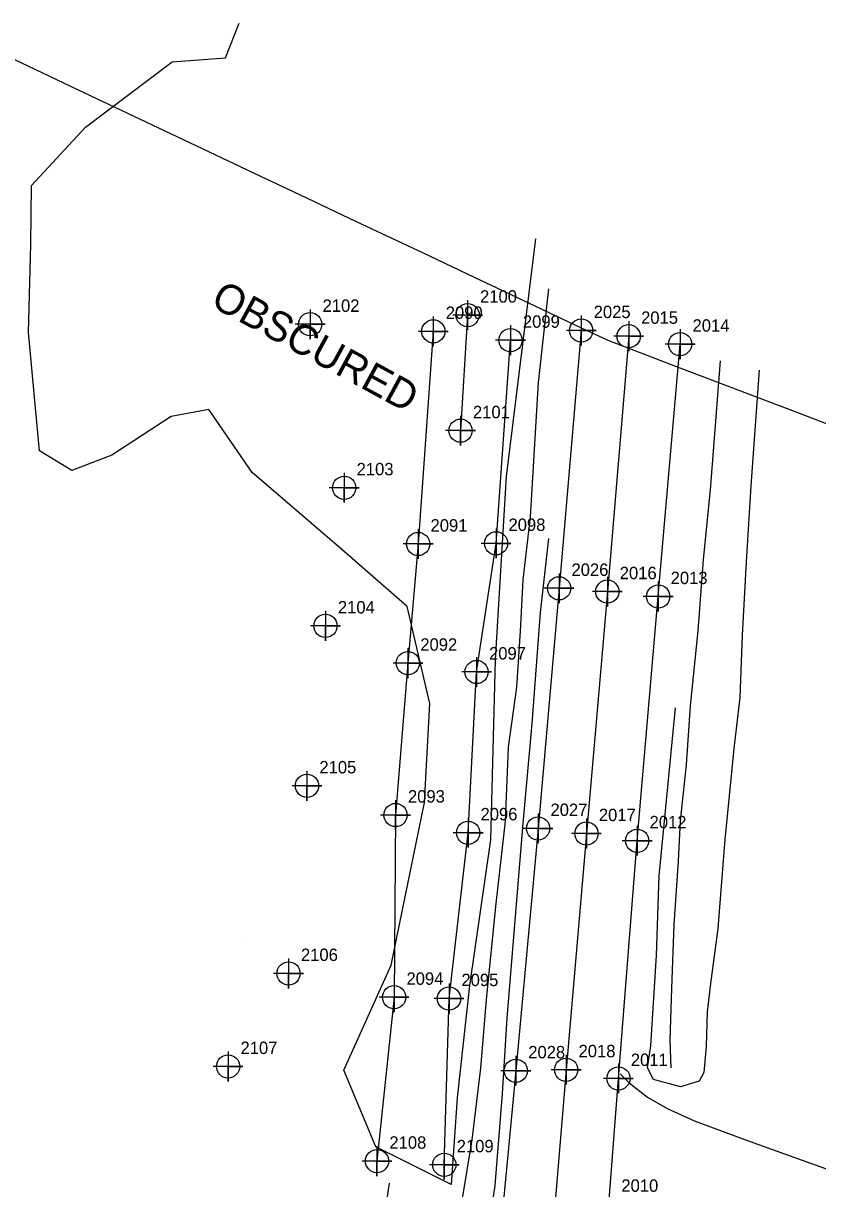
# Model space of a CAD drawing. Extents: x 1497074 to 1501343, y 481943 to 486114.
# Drawn here: x 1499836.8 to 1499996.8, y 482891.4 to 483126.1 of the extents above; entities that cross this region are included whole.
import ezdxf

# ---------------------------------------------------------------- set-up
doc = ezdxf.new("R2010")
doc.units = 0
for name, color, linetype in [('Exist DTM Breakline', 7, 'Continuous'), ('Exist DTM Breakline Cogo Number', 7, 'Continuous'), ('Exist DTM Breakline Cogo Point CELL', 7, 'Continuous'), ('Exist DTM Crownline', 7, 'Continuous'), ('Exist DTM Crownline Cogo Number', 7, 'Continuous'), ('Exist DTM Crownline Cogo Point CELL', 7, 'Continuous'), ('Exist DTM Regular Point CELL', 7, 'Continuous'), ('Exist DTM Regular Point Cogo Number', 7, 'Continuous'), ('Exist Roads EOP', 7, 'Continuous'), ('Exist Roads EOP Cogo Number', 7, 'Continuous'), ('Exist Roads EOP Cogo Point CELL', 7, 'Continuous'), ('PH Exist DTM Boundary', 7, 'Continuous'), ('PH Exist DTM Breakline', 7, 'Continuous'), ('PH Exist DTM Obscure Area', 7, 'Continuous'), ('PH Exist DTM Obscure Area Text', 7, 'Continuous'), ('PH Exist DTM Point', 7, 'Continuous')]:
    doc.layers.add(name, color=color, linetype=linetype)

msp = doc.modelspace()

# ---------------------------------------------------------------- linework, layer by layer
at = {"layer": 'Exist DTM Breakline'}
msp.add_line((1499926.3, 483067.35), (1499924.87, 483044.07), dxfattribs=at)
for points in [[(1499919.39, 483064.07), (1499916.33, 483021.24), (1499914.27, 482997.24), (1499911.78, 482966.64), (1499911.48, 482929.95), (1499908.04, 482896.93)], [(1499921.6, 482896.2), (1499922.55, 482929.68), (1499926.4, 482963.07), (1499928.11, 482995.46), (1499932.03, 483021.37), (1499934.93, 483062.29)]]:
    msp.add_lwpolyline(points, dxfattribs=at)
at = {"layer": 'Exist DTM Breakline Cogo Point CELL'}
for points in [[(1499926.3, 483070.35), (1499926.3, 483064.35), (1499926.3, 483067.35), (1499929.3, 483067.35), (1499923.3, 483067.35)], [(1499919.39, 483067.07), (1499919.39, 483061.07), (1499919.39, 483064.07), (1499922.39, 483064.07), (1499916.39, 483064.07)], [(1499934.93, 483065.29), (1499934.93, 483059.29), (1499934.93, 483062.29), (1499937.93, 483062.29), (1499931.93, 483062.29)], [(1499924.87, 483047.07), (1499924.87, 483041.07), (1499924.87, 483044.07), (1499927.87, 483044.07), (1499921.87, 483044.07)], [(1499916.33, 483024.24), (1499916.33, 483018.24), (1499916.33, 483021.24), (1499919.33, 483021.24), (1499913.33, 483021.24)], [(1499932.03, 483024.37), (1499932.03, 483018.37), (1499932.03, 483021.37), (1499935.03, 483021.37), (1499929.03, 483021.37)], [(1499914.27, 483000.24), (1499914.27, 482994.24), (1499914.27, 482997.24), (1499917.27, 482997.24), (1499911.27, 482997.24)], [(1499928.11, 482998.46), (1499928.11, 482992.46), (1499928.11, 482995.46), (1499931.11, 482995.46), (1499925.11, 482995.46)], [(1499911.78, 482969.64), (1499911.78, 482963.64), (1499911.78, 482966.64), (1499914.78, 482966.64), (1499908.78, 482966.64)], [(1499926.4, 482966.07), (1499926.4, 482960.07), (1499926.4, 482963.07), (1499929.4, 482963.07), (1499923.4, 482963.07)], [(1499911.48, 482932.95), (1499911.48, 482926.95), (1499911.48, 482929.95), (1499914.48, 482929.95), (1499908.48, 482929.95)], [(1499922.55, 482932.68), (1499922.55, 482926.68), (1499922.55, 482929.68), (1499925.55, 482929.68), (1499919.55, 482929.68)], [(1499908.04, 482899.93), (1499908.04, 482893.93), (1499908.04, 482896.93), (1499911.04, 482896.93), (1499905.04, 482896.93)], [(1499921.6, 482899.2), (1499921.6, 482893.2), (1499921.6, 482896.2), (1499924.6, 482896.2), (1499918.6, 482896.2)]]:
    msp.add_lwpolyline(points, dxfattribs=at)
for centre in [(1499926.3, 483067.35), (1499919.39, 483064.07), (1499934.93, 483062.29), (1499924.87, 483044.07), (1499916.33, 483021.24), (1499932.03, 483021.37), (1499914.27, 482997.24), (1499928.11, 482995.46), (1499911.78, 482966.64), (1499926.4, 482963.07), (1499911.48, 482929.95), (1499922.55, 482929.68), (1499908.04, 482896.93), (1499921.6, 482896.2)]:
    msp.add_circle(centre, 2.34, dxfattribs=at)
at = {"layer": 'Exist DTM Crownline'}
msp.add_lwpolyline([(1499958.74, 483063.09), (1499954.44, 483011.65), (1499950.23, 482962.92), (1499946.14, 482915.34), (1499941.96, 482865.48), (1499937.54, 482815.31), (1499932.53, 482760.35), (1499932.32, 482757.09)], dxfattribs=at)
at = {"layer": 'Exist DTM Crownline Cogo Point CELL'}
for points in [[(1499958.74, 483066.09), (1499958.74, 483060.09), (1499958.74, 483063.09), (1499961.74, 483063.09), (1499955.74, 483063.09)], [(1499954.44, 483014.65), (1499954.44, 483008.65), (1499954.44, 483011.65), (1499957.44, 483011.65), (1499951.44, 483011.65)], [(1499950.23, 482965.92), (1499950.23, 482959.92), (1499950.23, 482962.92), (1499953.23, 482962.92), (1499947.23, 482962.92)], [(1499946.14, 482918.34), (1499946.14, 482912.34), (1499946.14, 482915.34), (1499949.14, 482915.34), (1499943.14, 482915.34)]]:
    msp.add_lwpolyline(points, dxfattribs=at)
for centre in [(1499958.74, 483063.09), (1499954.44, 483011.65), (1499950.23, 482962.92), (1499946.14, 482915.34)]:
    msp.add_circle(centre, 2.34, dxfattribs=at)
at = {"layer": 'Exist DTM Regular Point CELL'}
for points in [[(1499894.58, 483068.5), (1499894.58, 483062.5), (1499894.58, 483065.5), (1499897.58, 483065.5), (1499891.58, 483065.5)], [(1499901.44, 483035.57), (1499901.44, 483029.57), (1499901.44, 483032.57), (1499904.44, 483032.57), (1499898.44, 483032.57)], [(1499897.67, 483007.75), (1499897.67, 483001.75), (1499897.67, 483004.75), (1499900.67, 483004.75), (1499894.67, 483004.75)], [(1499893.94, 482975.53), (1499893.94, 482969.53), (1499893.94, 482972.53), (1499896.94, 482972.53), (1499890.94, 482972.53)], [(1499890.23, 482937.73), (1499890.23, 482931.73), (1499890.23, 482934.73), (1499893.23, 482934.73), (1499887.23, 482934.73)], [(1499878.05, 482919), (1499878.05, 482913), (1499878.05, 482916), (1499881.05, 482916), (1499875.05, 482916)]]:
    msp.add_lwpolyline(points, dxfattribs=at)
for centre in [(1499894.58, 483065.5), (1499901.44, 483032.57), (1499897.67, 483004.75), (1499893.94, 482972.53), (1499890.23, 482934.73), (1499878.05, 482916)]:
    msp.add_circle(centre, 2.34, dxfattribs=at)
at = {"layer": 'Exist Roads EOP'}
for points in [[(1499949.19, 483064.24), (1499944.72, 483012.31), (1499940.49, 482963.95), (1499936.01, 482915.13), (1499931.45, 482867.17), (1499924.58, 482816.71), (1499922.02, 482806.45), (1499917.89, 482798.05), (1499910.37, 482788.35), (1499905.04, 482784.05), (1499895.66, 482779.46), (1499886.2, 482778), (1499874.11, 482778.69), (1499823.96, 482797.88), (1499778.75, 482816.38), (1499731.6, 482836.87), (1499686.89, 482857.05)], [(1500333.95, 482612.22), (1500284.36, 482629.66), (1500236.85, 482646.79), (1500185.72, 482665.19), (1500183.6, 482666.66), (1500153.81, 482677.07), (1500131.68, 482684.8), (1500082.43, 482702.46), (1500031.71, 482720.79), (1499985.76, 482737.42), (1499982.67, 482738.92), (1499980.46, 482741.68), (1499966.94, 482755.42), (1499959.88, 482766), (1499955.46, 482776.15), (1499952.81, 482784.59), (1499951.94, 482792.64), (1499951.08, 482814.55), (1499953.05, 482864.42), (1499954.76, 482888.25), (1499956.67, 482913.59), (1499960.45, 482961.46), (1499964.69, 483010.66), (1499969.1, 483061.5)]]:
    msp.add_lwpolyline(points, dxfattribs=at)
at = {"layer": 'Exist Roads EOP Cogo Point CELL'}
for points in [[(1499949.19, 483067.24), (1499949.19, 483061.24), (1499949.19, 483064.24), (1499952.19, 483064.24), (1499946.19, 483064.24)], [(1499969.1, 483064.5), (1499969.1, 483058.5), (1499969.1, 483061.5), (1499972.1, 483061.5), (1499966.1, 483061.5)], [(1499944.72, 483015.31), (1499944.72, 483009.31), (1499944.72, 483012.31), (1499947.72, 483012.31), (1499941.72, 483012.31)], [(1499964.69, 483013.66), (1499964.69, 483007.66), (1499964.69, 483010.66), (1499967.69, 483010.66), (1499961.69, 483010.66)], [(1499940.49, 482966.95), (1499940.49, 482960.95), (1499940.49, 482963.95), (1499943.49, 482963.95), (1499937.49, 482963.95)], [(1499960.45, 482964.46), (1499960.45, 482958.46), (1499960.45, 482961.46), (1499963.45, 482961.46), (1499957.45, 482961.46)], [(1499936.01, 482918.13), (1499936.01, 482912.13), (1499936.01, 482915.13), (1499939.01, 482915.13), (1499933.01, 482915.13)], [(1499956.67, 482916.59), (1499956.67, 482910.59), (1499956.67, 482913.59), (1499959.67, 482913.59), (1499953.67, 482913.59)]]:
    msp.add_lwpolyline(points, dxfattribs=at)
for centre in [(1499949.19, 483064.24), (1499969.1, 483061.5), (1499944.72, 483012.31), (1499964.69, 483010.66), (1499940.49, 482963.95), (1499960.45, 482961.46), (1499936.01, 482915.13), (1499956.67, 482913.59)]:
    msp.add_circle(centre, 2.34, dxfattribs=at)
at = {"layer": 'PH Exist DTM Boundary'}
msp.add_lwpolyline([(1500009.09, 483041.44), (1499993.01, 483047.57), (1499989.09, 483049.06), (1499982.72, 483051.49), (1499969.09, 483056.68), (1499960.7, 483059.88), (1499954.58, 483062.21), (1499954.58, 483062.21), (1499949.09, 483064.81), (1499934.96, 483071.49), (1499930.97, 483073.37), (1499929.09, 483074.27), (1499917.39, 483079.8), (1499909.09, 483083.72), (1499903.81, 483086.22), (1499892.66, 483091.49), (1499889.09, 483093.18), (1499885.89, 483094.69), (1499869.09, 483102.63), (1499850.36, 483111.49), (1499849.09, 483112.09), (1499847.95, 483112.63), (1499829.09, 483121.55)], dxfattribs=at)
at = {"layer": 'PH Exist DTM Breakline'}
for points in [[(1499942.62, 483072.62), (1499940.52, 483053.77), (1499938.93, 483026.68), (1499937.41, 483014.04), (1499936.89, 483003.67), (1499936.16, 482992.43), (1499934.46, 482980.32), (1499933.85, 482965.43), (1499931.98, 482948.82), (1499930.01, 482929.49), (1499928.87, 482915.66), (1499927.12, 482901.19), (1499925.17, 482889.42)], [(1499984.99, 483056.22), (1499983.34, 483032.93), (1499982.39, 483017.66), (1499981.57, 483002.88), (1499981.1, 482990.35), (1499979.94, 482980.07), (1499979, 482970.51), (1499978.11, 482961.71), (1499977.49, 482954.07), (1499976.72, 482943.79), (1499975.22, 482932.69), (1499974.53, 482927.02), (1499974.33, 482920.01), (1499973.86, 482914.75), (1499972.94, 482913.06), (1499969.19, 482911.91), (1499963.77, 482913.35), (1499962.55, 482915.74), (1499963.2, 482920.19)], [(1499977.14, 483058.13), (1499975.18, 483032.14), (1499973.75, 483018.11), (1499972.64, 483003.76), (1499971.14, 482988.67), (1499970.31, 482976.78), (1499969.08, 482965.49), (1499968.72, 482957.36), (1499967.83, 482944.57), (1499967.34, 482931.7), (1499967.05, 482921.32), (1499967.22, 482915.69)], [(1499881.57, 482782.86), (1499889.62, 482782.75), (1499896.56, 482784.64), (1499903.43, 482787.74), (1499909.34, 482792.34), (1499913.56, 482798.2), (1499917.47, 482803.77), (1499919.36, 482810.89), (1499921.77, 482822.35), (1499923.8, 482835.12), (1499925.62, 482847.36), (1499928.12, 482864.6), (1499929.76, 482877.93), (1499931.83, 482891.99), (1499933.34, 482910.51), (1499934.27, 482925.74), (1499937.4, 482964.22), (1499939.33, 482985.05), (1499941.01, 483007.43), (1499942.66, 483022.35)], [(1499963.2, 482920.19), (1499964.31, 482938.35), (1499964.9, 482954.39), (1499966.62, 482972.3), (1499968.19, 482988.25)], [(1499957.02, 482914.54), (1499958.81, 482912.69), (1499962.54, 482909.78), (1499966.51, 482907.56), (1499972.1, 482905.01), (1499983.23, 482900.88), (1499997.95, 482895.57), (1500012.89, 482890.28), (1500036.47, 482882.13), (1500053.99, 482875.96), (1500083.65, 482865.7), (1500105.38, 482858.07), (1500123.06, 482852.19), (1500135.58, 482847.54), (1500139.93, 482846.87), (1500147.82, 482845.98), (1500154.76, 482845.59), (1500161.06, 482844.73), (1500169.77, 482841.96), (1500178.21, 482838.66), (1500188.63, 482834.5)], [(1499909.32, 482883.91), (1499910.55, 482892.52)]]:
    msp.add_lwpolyline(points, dxfattribs=at)
at = {"layer": 'PH Exist DTM Obscure Area'}
msp.add_lwpolyline([(1499939.99, 483082.68), (1499934.07, 483034.86), (1499931.82, 482997.88), (1499930.88, 482961.66), (1499926.7, 482932.31), (1499924.2, 482909.7), (1499922.99, 482892.24), (1499907.78, 482899.83), (1499901.38, 482915.22), (1499910.87, 482936.43), (1499917.63, 482969.15), (1499918.66, 482989.11), (1499914.1, 483008.65), (1499900.99, 483020.15), (1499882.91, 483035.63), (1499874.18, 483048.34), (1499866.56, 483046.94), (1499854.66, 483039.15), (1499846.61, 483036.04), (1499840.05, 483040.01), (1499837.85, 483063.84), (1499838.35, 483081.54), (1499838.44, 483093.48), (1499849.36, 483105.18), (1499866.8, 483118.36), (1499877.51, 483119.19), (1499880.26, 483126.12)], dxfattribs=at)
at = {"layer": 'PH Exist DTM Point'}
for p, q in [((1499851.11, 483108.94), (1499851.11, 483108.94)), ((1499993.12, 483051.12), (1499993.12, 483051.12)), ((1499870.84, 483046.61), (1499870.84, 483046.61)), ((1499850.5, 483032.19), (1499850.5, 483032.19)), ((1499865.5, 483032.19), (1499865.5, 483032.19)), ((1499880.49, 483032.19), (1499880.49, 483032.19)), ((1499991.55, 483031.29), (1499991.55, 483031.29)), ((1499850.5, 483017.19), (1499850.5, 483017.19)), ((1499865.5, 483017.19), (1499865.5, 483017.19)), ((1499880.5, 483017.19), (1499880.5, 483017.19)), ((1499895.5, 483017.19), (1499895.5, 483017.19)), ((1499991.37, 483014.53), (1499991.37, 483014.53)), ((1499850.5, 483002.19), (1499850.5, 483002.19)), ((1499865.5, 483002.19), (1499865.5, 483002.19)), ((1499880.5, 483002.19), (1499880.5, 483002.19)), ((1499895.5, 483002.19), (1499895.5, 483002.19)), ((1499910.5, 483002.19), (1499910.5, 483002.19)), ((1499990.74, 483000.75), (1499990.74, 483000.75)), ((1499850.5, 482987.19), (1499850.5, 482987.19)), ((1499865.5, 482987.19), (1499865.5, 482987.19)), ((1499880.5, 482987.19), (1499880.5, 482987.19)), ((1499895.5, 482987.19), (1499895.5, 482987.19)), ((1499910.5, 482987.19), (1499910.5, 482987.19)), ((1499985.51, 482987.18), (1499985.51, 482987.18)), ((1499850.5, 482972.19), (1499850.5, 482972.19)), ((1499865.5, 482972.19), (1499865.5, 482972.19)), ((1499880.5, 482972.19), (1499880.5, 482972.19)), ((1499895.5, 482972.19), (1499895.5, 482972.19)), ((1499910.5, 482972.19), (1499910.5, 482972.19)), ((1499985.5, 482972.19), (1499985.5, 482972.19)), ((1499918.68, 482962.93), (1499918.68, 482962.93)), ((1499850.5, 482957.19), (1499850.5, 482957.19)), ((1499865.5, 482957.19), (1499865.5, 482957.19)), ((1499880.5, 482957.19), (1499880.5, 482957.19)), ((1499895.5, 482957.19), (1499895.5, 482957.19)), ((1499910.5, 482957.19), (1499910.5, 482957.19)), ((1499985.5, 482957.19), (1499985.5, 482957.19)), ((1499850.5, 482942.19), (1499850.5, 482942.19)), ((1499865.5, 482942.19), (1499865.5, 482942.19)), ((1499880.5, 482942.19), (1499880.5, 482942.19)), ((1499895.5, 482942.19), (1499895.5, 482942.19)), ((1499985.5, 482942.19), (1499985.5, 482942.19)), ((1499908.32, 482938.19), (1499908.32, 482938.19)), ((1499850.5, 482927.19), (1499850.5, 482927.19)), ((1499865.5, 482927.19), (1499865.5, 482927.19)), ((1499880.5, 482927.19), (1499880.5, 482927.19)), ((1499895.5, 482927.19), (1499895.5, 482927.19)), ((1499985.5, 482927.19), (1499985.5, 482927.19)), ((1499850.5, 482912.19), (1499850.5, 482912.19)), ((1499865.5, 482912.19), (1499865.5, 482912.19)), ((1499880.5, 482912.19), (1499880.5, 482912.19)), ((1499895.5, 482912.19), (1499895.5, 482912.19)), ((1499992.85, 482912.36), (1499992.85, 482912.36)), ((1499850.5, 482897.19), (1499850.5, 482897.19)), ((1499865.5, 482897.19), (1499865.5, 482897.19)), ((1499895.5, 482897.19), (1499895.5, 482897.19)), ((1499883.28, 482895.67), (1499883.28, 482895.67))]:
    msp.add_line(p, q, dxfattribs=at)

# ---------------------------------------------------------------- texts
at = {"layer": 'Exist DTM Breakline Cogo Number'}
for s, p in [('2100', (1499928.8, 483069.85)), ('2090', (1499921.89, 483066.58)), ('2099', (1499937.43, 483064.79)), ('2101', (1499927.37, 483046.57)), ('2091', (1499918.83, 483023.74)), ('2098', (1499934.53, 483023.87)), ('2092', (1499916.77, 482999.74)), ('2097', (1499930.61, 482997.96)), ('2093', (1499914.28, 482969.15)), ('2096', (1499928.9, 482965.57)), ('2094', (1499913.98, 482932.45)), ('2095', (1499925.05, 482932.18)), ('2108', (1499910.54, 482899.43)), ('2109', (1499924.1, 482898.7))]:
    msp.add_text(s, height=2.5, dxfattribs=at).set_placement(p)
at = {"layer": 'Exist DTM Crownline Cogo Number'}
for s, p in [('2015', (1499961.24, 483065.59)), ('2016', (1499956.94, 483014.15)), ('2017', (1499952.73, 482965.42)), ('2018', (1499948.64, 482917.85))]:
    msp.add_text(s, height=2.5, dxfattribs=at).set_placement(p)
at = {"layer": 'Exist DTM Regular Point Cogo Number'}
for s, p in [('2102', (1499897.08, 483068)), ('2103', (1499903.94, 483035.07)), ('2104', (1499900.17, 483007.25)), ('2105', (1499896.44, 482975.03)), ('2106', (1499892.73, 482937.24)), ('2107', (1499880.55, 482918.5))]:
    msp.add_text(s, height=2.5, dxfattribs=at).set_placement(p)
at = {"layer": 'Exist Roads EOP Cogo Number'}
for s, p in [('2025', (1499951.69, 483066.74)), ('2014', (1499971.6, 483064)), ('2026', (1499947.22, 483014.81)), ('2013', (1499967.19, 483013.16)), ('2027', (1499942.99, 482966.45)), ('2012', (1499962.95, 482963.97)), ('2028', (1499938.51, 482917.63)), ('2011', (1499959.17, 482916.09)), ('2010', (1499957.26, 482890.75))]:
    msp.add_text(s, height=2.5, dxfattribs=at).set_placement(p)
at = {"layer": 'PH Exist DTM Obscure Area Text'}
msp.add_text('OBSCURED', height=6, rotation=331.4345, dxfattribs=at).set_placement((1499874.28, 483069.3))

doc.saveas('drawing.dxf')
